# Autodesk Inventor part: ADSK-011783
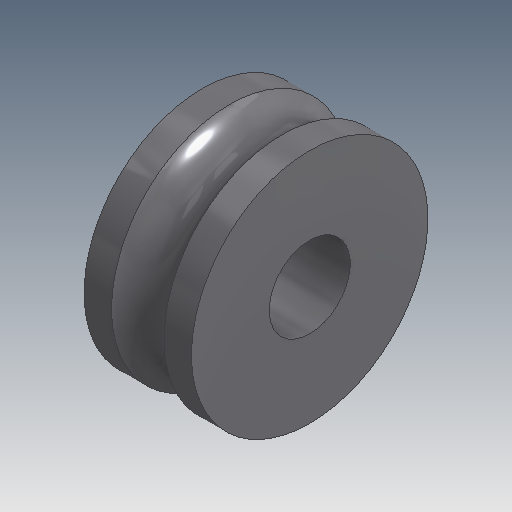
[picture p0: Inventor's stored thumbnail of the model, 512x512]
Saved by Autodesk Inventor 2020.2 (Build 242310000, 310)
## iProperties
Created: 1999-12
Part Number: ADSK-011783
Material: Acier (alliage faible hypertrempé)
Document SubType Name: Modeling
Designer: tgregory
Density: 7.84 g/cm^3
Appearance: Metal-Steel(Polish)
Mass: 97.5856 g
Surface Area: 41.0163 cm^2
Volume: 12.4471 cm^3
Control State: 0
Checked Out: False
Master: False
Shininess: 0.0
Length Units: 11269
Angle Units: 11279
Time Units: 11290
Mass Units: 11283
Length Display Precision: 3
Angle Display Precision: 2
Compacted: True
Dimensions: 35x35x15,9 mm
Mass: 0,098 kg
VLT_Material: Acier (alliage faible hypertrempé)
Density: 0.0
Volumn: 0.0
Area: 0.0
PropertySet Name: Model Information
Author: tgregory
Revision Number: -
Title: ADSK-011783
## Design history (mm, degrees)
node "Revolution1" dims "d5" = 360 deg
node "Solide1"
node "Corps solides"
node "Corps surfaciques"
sketch "Sketch1"
  geometry: L1 (0, 0)-(29.665, 0) reference; L2 (0, 6)-(15.9, 6); L3 (15.9, 6)-(15.9, 17.5) reference; L4 (0, 17.5)-(0, 6) reference; L5 (7.95, 6)-(7.95, 20.65); L6 (15.9, 17.5)-(11.833, 17.5); L7 (4.067, 17.5)-(0, 17.5) reference; A1 r 5 centre (7.95, 20.65) between (4.067, 17.5) and (11.833, 17.5)
  constraints: 14 end point, 4 horizontal, 3 parallel, 3 perpendicular, 2 point on circle, 2 vertical, 1 centre point, 1 midpoint
  dimensions: "d0" = 6 distance between parallel lines of L2 L1; "d2" = 15.9 distance of L3.end L4.start; "d3" = 10 diameter of A1; "d4" = 20.65 distance from line of L5.end L1
other parameters: "d1" = 17.5
